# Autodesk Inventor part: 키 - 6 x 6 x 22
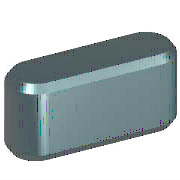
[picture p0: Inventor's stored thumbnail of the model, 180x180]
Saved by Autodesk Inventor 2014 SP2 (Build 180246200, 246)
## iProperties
IsCustomPart: 1
Created: 2012-02
Part Number: 키 - 6 x 6 x 22
Material: 강철, 연강
Description: 키 및 해당 키홈
Document SubType Name: Modeling
Standard: KS B 1311
Designer: mduedu
Standards Organization: KS
Language: ko-KR
Size Designation: 6 x 6 x 22
Categories: <MemberInstance><Categories><Category DisplayName="샤프트 부품" InternalName="7f7aeb1f-a693-4053-b835-cee3144e0d98" Mnemonic="SHFT"><Category DisplayName="키" Interna
Density: 7.86 g/cm^3
Mass: 5.79788 g
Surface Area: 5.294 cm^2
Volume: 0.737644 cm^3
Appearance: 강철
Author: mduedu
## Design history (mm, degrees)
workplane "Work Plane1"
workplane "Work Plane2"
sketch "스케치1"
  geometry: L1 (3, 3)-(19, 3); L2 (19, -3)-(3, -3); L3 (0, 9.4)-(0, -7.4) reference; L4 (-5, 0)-(30, 0) reference; L5 (22, 0)-(22, 7); A1 r 3 centre (3, 0) between (3, 3) and (3, -3); A2 r 3 centre (19, 0) between (19, -3) and (19, 3)
  constraints: 6 end point, 5 point on circle, 4 tangent, 3 point on line, 2 centre point, 1 horizontal, 1 parallel, 1 perpendicular
  dimensions: "d0" = 3 radius of A1 (= 0.5 x PB); "d13" = 3 radius of A2 (= 0.5 x PB); "d14" = 22 distance between parallel lines of L5 L3 (= NLG)
extrude "본체1" new body sketch "스케치1" taper "d3" = 0 deg; stored distance "d4" = 10
workplane "Work Plane3"
body "Solid1"
chamfer "모따기1" distance "d8" = 0.4 (= PHH); stored, may be unused: second distance "d9" = 0.4 (= PHH), angle "d15" = 45 deg
other parameters: "d1" = -3.5 (= -PNT), "d2" = 2.5 (= PH - PNT), "NLG" = 22 [user parameter; used in 3 equation terms], "PB" = 6 [user parameter; used in 2 equation terms], "PNT" = 3.5 [user parameter; used in 2 equation terms], "PH" = 6 [user parameter; used in 1 equation term], "PHH" = 0.4 [user parameter; used in 2 equation terms], "d10" = 0, "d16" = 0, "d17" = 0, "d18" = 0, "WDMIN" = 17 [user parameter], "PLB2" = 22 (= NLG) [user parameter], "WDMAX" = 22 [user parameter], "PLB1" = 22 (= NLG) [user parameter], "RR" = 0.16 [user parameter], "PUEB" = 2.8 [user parameter]
